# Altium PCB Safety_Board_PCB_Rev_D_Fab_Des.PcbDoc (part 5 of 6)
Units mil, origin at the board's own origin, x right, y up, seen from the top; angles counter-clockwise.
Board outline 11000 x 4400 mil, 6 copper layers (L1-TOP, L2-Plane, L3-Signal, L4-Signal, L5-Plane, L6-BOT); 712 components, 540 nets, 2214 pads, 875 vias.
Unrouted connection lines stored in the file: 3.
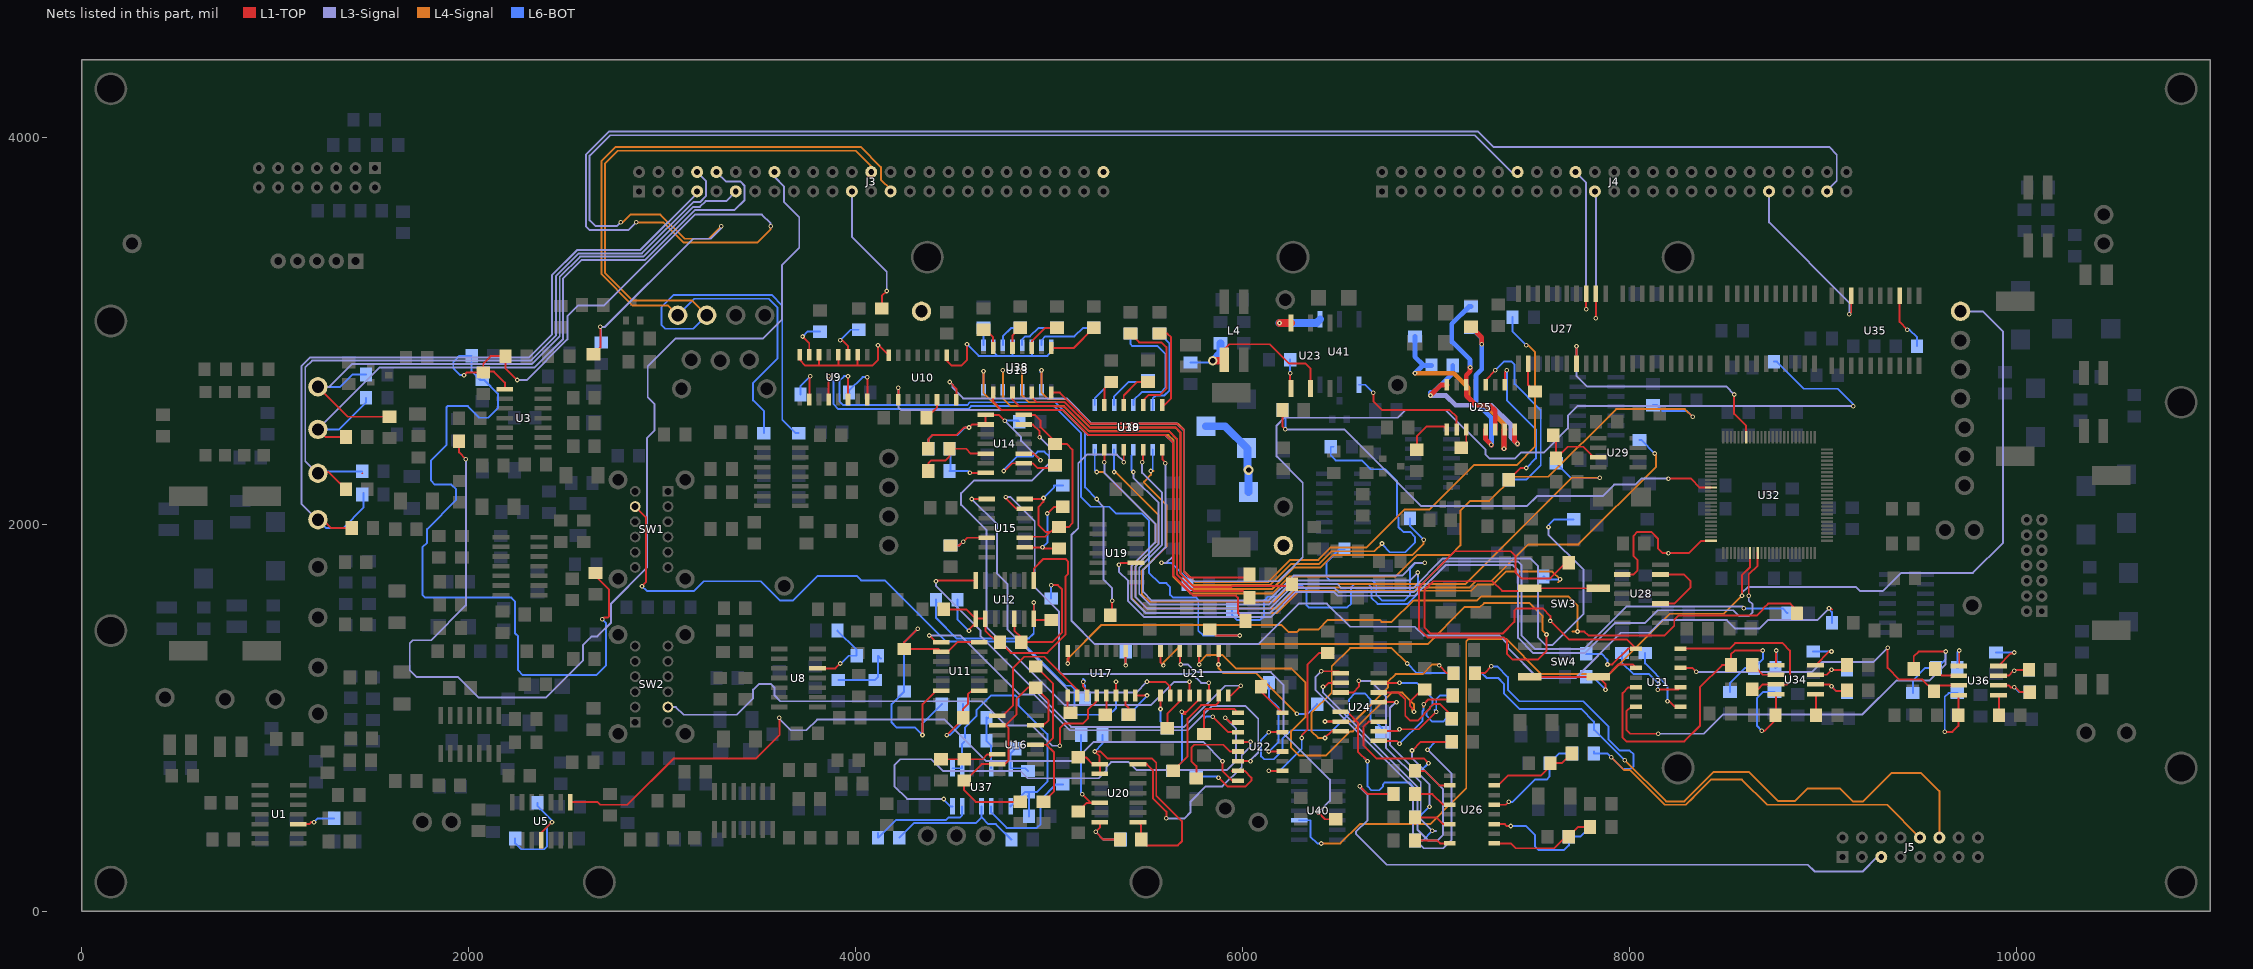
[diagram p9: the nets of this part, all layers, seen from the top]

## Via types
v1: diameter 24, hole 12, L1-TOP to L6-BOT, 720 vias
v2: diameter 50, hole 28, L1-TOP to L6-BOT, 138 vias
v3: diameter 28, hole 50, L1-TOP to L6-BOT, 17 vias

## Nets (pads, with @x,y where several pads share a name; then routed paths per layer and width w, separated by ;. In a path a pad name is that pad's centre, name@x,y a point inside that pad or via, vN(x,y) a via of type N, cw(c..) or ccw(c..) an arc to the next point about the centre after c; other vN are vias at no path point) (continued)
NetR83_2: R83.2 R266.1 R271.2 U11.2 U11.6 U11.14 | length 1737.2
  L1-TOP w10: v1(4320,1460) 4250,1390 R83.2@4250,1355.24 4426.46,1355.24 U11.2@4441.57,1340.12 4475,1340.12 4525,1390.12 U11.14@4638.43,1390.12 ; v1(4345,910.12) 4345,1070.12 U11.6@4415,1140.12
  L6-BOT w10: v1(4320,1460) 4250,1390 R266.1@4250,1135.24 4185,1070.24 4185,975 4210,950 4305.12,950 v1(4345,910.12) 4345,970.12 R271.2@4444.88,1070
NetR85_1: R85.1 U10.14 | length 115.7
  L1-TOP w10: R85.1@4364.88,2550 4420,2605.12 U10.14@4420,2642.84
NetR86_1: R86.1 R87.2 U14.5 | length 401.4
  L1-TOP w10: R87.2@4374.88,2275 4374.88,2314.88 4390,2330 4465,2330 4485.12,2350.12 R86.1@4485.12,2390 4485.24,2389.88 4570.12,2389.88 4595,2365 U14.5@4671.57,2365
NetR86_2: R86.2 R267.2 R276.1 U14.1 U14.2 U14.10 | length 1311.2
  L1-TOP w10: R86.2@4374.88,2390 4374.88,2439.88 4395,2460 4520,2460 4560,2500 v1(4585,2500) 4600,2515 U14.2@4671.57,2515 U14.1@4671.57,2565 ; U14.1@4666.69,2560.12 U14.1@4671.57,2565 ; v1(4770,2535) 4740,2565 U14.1@4671.57,2565 ; U14.10@4868.43,2365 4920,2365 v1(4955,2330)
  L3-Signal w10: v1(4770,2535) 4855,2450 4855,2430 v1(4955,2330)
  L6-BOT w10: R267.2@4374.88,2390 4374.88,2439.88 4395,2460 4525,2460 4565,2500 v1(4585,2500) ; v1(4770,2535) 4839.88,2535 R276.1@4844.88,2530 ; R276.1@4829.88,2535 R276.1@4844.88,2520
NetR89_1: R89.1 R269.2 U15.5 | length 311.5
  L1-TOP w10: R89.1@4514.88,1915 R89.1@4490,1890.12 4535.12,1890.12 4575,1930 U15.5@4676.57,1930
  L6-BOT w10: R269.2@4490,1890.12 4535.12,1890.12 v1(4555,1910)
NetR90_1: R90.1 R96.2 R265.2 U12.1 U12.2 U12.8 | length 1707.4
  L1-TOP w10: R90.1@4455.12,1560 4571.57,1560 U12.1@4620,1511.57 ; v1(4585,1450) 4585,1455 4620,1490 U12.1@4620,1511.57 ; U12.8@4920,1708.43 4920,1770 4970,1820 5085,1820 5098,1807 5098,1743 5085,1730 5085,1430 4990,1335 4799.88,1335 R96.2@4744.88,1390 4730,1390 4670,1450 U12.2@4670,1511.57 U12.1@4620,1511.57
  L6-BOT w10: R265.2@4525.12,1610 4525.12,1509.88 v1(4585,1450)
NetR91_2: R91.2 R94.1 U16.5 | length 322.9
  L1-TOP w10: R91.2@4440,785.12 4655.12,785.12 4680,810 U16.5@4731.57,810 ; 4695.12,795.12 U16.5@4710,810
NetR92_2: R92.2 R271.1 U11.9 | length 526.4
  L1-TOP w10: v1(4470,910) 4555.12,995.12 4555.12,1045.24 4580,1070.12 4580,1120.12 4600,1140.12 U11.9@4638.43,1140.12
  L6-BOT w10: v1(4470,910) 4485,910 4555.12,980.12 R271.1@4555.12,1070
NetR93_1: R93.1 U13.7 | length 125.4
  L1-TOP w10: R93.1@4660,3014.88 4710,2964.88 U13.7@4710,2910.16
NetR94_2: R94.2 R98.2 R99.1 U16.2 U16.6 U16.13 | length 1382.6
  L1-TOP w10: U16.2@4731.57,960 4775,960 ; R99.1@4850,565.12 4619.88,565.12 4560,625 R94.2@4560,674.88 4564.88,674.88 4650,760 4770,760 4790,780 4790,945 4775,960 ; U16.13@4970,960 4995,985 4995,1089.88 R98.2@4930,1154.88 4889.88,1154.88 4830,1095 4830,1015 4775,960
NetR95_1: R95.1 U13.5 | length 121.3
  L1-TOP w10: U13.5@4810,2910.16 4810,2974.88 R95.1@4850,3014.88
NetR96_1: R96.1 R281.2 U12.5 | length 724.9
  L1-TOP w10: U12.5@4820,1511.57 4820,1450 4855.12,1414.88 R96.1@4855.12,1390 5015,1390 5065,1440 5065,1665 5045,1685 v1(5010,1685)
  L6-BOT w10: R281.2@5010,1615.12 v1(5010,1685)
NetR97_1: R97.1 R104.2 U15.9 | length 501.1
  L1-TOP w10: U15.9@4873.43,1880 v1(4965,1880) 4970.12,1874.88 R97.1@5050,1874.88 ; v1(4990,2055) 5024.88,2089.88 R104.2@5070,2089.88 ; R97.1@5039.88,1880 R97.1@5070,1849.88
  L6-BOT w10: v1(4965,1880) 4990,1905 v1(4990,2055)
NetR97_2: R97.2 R103.2 R283.1 U14.14 U15.10 U15.14 | length 1466.5
  L1-TOP w10: U14.14@4868.43,2565 4925,2565 4955,2535 4955,2500 5030,2425 R103.2@5030,2415.12 5089.88,2415.12 5120,2385 5120,2005 5100.12,1985.12 5030.12,1985.12 4980,1935 4878.43,1935 U15.10@4873.43,1930 ; U15.14@4873.43,2130 4965,2130 v1(4970,2135) 4970,2115 4945,2090 4945,1995 4979.88,1960.12 5005.12,1960.12
  L6-BOT w10: v1(4970,2135) 5025.12,2190.12 5025.12,2200.12 R283.1@5070,2200.12
NetR98_1: R98.1 R100.2 U16.11 | length 847.7
  L1-TOP w10: U16.11@4928.43,860 4985,860 ; R98.1@4930,1265.12 5020,1175.12 5020,895 4985,860 ; R100.2@4970,565.12 5025,620.12 5025,820 4985,860
NetR101_1: R101.1 U13.3 | length 193.8
  L1-TOP w10: U13.3@4910,2910.16 4910,2945 4979.88,3014.88 R101.1@5040,3014.88
NetR102_2: R102.2 R265.1 U12.7 | length 997.2
  L1-TOP w10: U12.7@4915,1516.57 U12.7@4920,1511.57 v1(4920,1595) ; U12.7@4920,1511.57 4926.69,1504.88 R102.2@5010,1504.88
  L6-BOT w10: R265.1@4414.88,1610 4414.88,1515.12 4520,1410 4895,1410 4920,1435 v1(4920,1595)
NetR103_1: R103.1 R282.2 U14.9 | length 645.3
  L1-TOP w10: v1(4765,2275) 4770,2275 4810,2315 4915,2315 4940,2290 5015.12,2290 R103.1@5030,2304.88
  L6-BOT w10: v1(4765,2275) 4765,2280 4835,2350 4915,2350 4940,2375 4975,2375 5000,2350 5000,2334.88 R282.2@5030,2304.88
NetR105_1: R105.1 U17.1 | length 95.9
  L1-TOP w10: U17.1@5095,1114.84 5095,1040.12 R105.1@5110,1025.12
NetR106_1: R106.1 R115.2 R289.2 U20.1 U20.2 U20.8 | length 1499.2
  L1-TOP w10: R106.1@5150,795.12 5189.88,795.12 5225,760 U20.1@5261.57,760 U20.2@5261.57,710 ; U20.1@5260,760 5260,800 v1(5235,825) 5265,825 5300,790 5530,790 5553,767 5553,597 5685,465 5685,360 5665,340 5505.12,340 R115.2@5475.12,370 ; U20.8@5458.43,460 5475.12,443.31 R115.2@5475.12,370 ; R115.2@5490,370 R115.2@5475.12,370
  L6-BOT w10: v1(5235,825) 5275.12,865.12 R289.2@5275.12,910
NetR107_2: R107.2 R289.1 U20.5 | length 500.9
  L1-TOP w10: R107.2@5150,515.12 5194.88,560 U20.5@5261.57,560 ; v1(5170,605) 5215,560
  L6-BOT w10: R289.1@5164.88,910 5164.88,610.12 v1(5170,605)
NetR108_1: R108.1 U13.1 | length 263.4
  L1-TOP w10: U13.1@5010,2910.16 5125.28,2910.16 R108.1@5230,3014.88
NetR109_2: R109.2 U9.14 | length 2636.3
  L1-TOP w10: U9.14@3960,2644.84 v1(3960,2765) ; R109.2@5315.12,1530 5325,1539.88 v1(5325,1605)
  L3-Signal w10: v1(5245,2130) 5245,2125 5280,2090 5280,1715 5325,1670 v1(5325,1605)
  L6-BOT w10: v1(3960,2765) 3940,2765 3915,2740 3915,2635 3935,2615 4575,2615 4590,2630 5030,2630 5185,2475 5185,2190 v1(5245,2130)
NetR110_1: R110.1 U17.5 | length 101.8
  L1-TOP w10: R110.1@5290,1015.12 5295,1020.12 U17.5@5295,1114.84
NetR111_1: R111.1 U18.7 | length 134.2
  L1-TOP w10: U18.7@5285,2615.16 5285,2699.88 R111.1@5320,2734.88
NetR112_1: R112.1 U18.3 | length 598.6
  L1-TOP w10: R112.1@5420,2984.88 5464.88,2940 5580,2940 5605,2915 5605,2700 5573,2668 5513,2668 5485,2640 U18.3@5485,2615.16
NetR114_2: R114.2 U17.7 | length 105.9
  L1-TOP w10: U17.7@5395,1114.84 5395,1065 5410,1050 R114.2@5410,1015.12
NetR115_1: R115.1 R293.2 U20.7 | length 348.3
  L1-TOP w10: v1@5242.5,412.5 5261.57,431.57 U20.7@5261.57,460 ; v1@5245,410 v1(5240,410) 5280,370 R115.1@5364.88,370
  L6-BOT w10: v1(5240,410) 5280,370 R293.2@5369.88,370
NetR116_1: R116.1 U18.5 | length 203.8
  L1-TOP w10: U18.5@5385,2615.16 5385,2665 5454.88,2734.88 R116.1@5510,2734.88
NetR118_1: R118.1 U18.1 | length 442.7
  L1-TOP w10: R118.1@5570,2984.88 5610.12,2984.88 5630,2965 5630,2650 5595.16,2615.16 U18.1@5585,2615.16
NetR119_1: R119.1 U21.3 | length 213.8
  L1-TOP w10: R119.1@5610,935 5610,1020 5675,1085 U21.3@5675,1114.84 U21.3@5680,1109.84
NetR120_1: R120.1 U21.7 | length 530.8
  L1-TOP w10: R120.1@5640.12,725.24 5715,800.12 5715,995 5785,1065 5860,1065 5875,1080 U21.7@5875,1114.84
NetR121_1: R121.1 U22.5 | length 430.8
  L1-TOP w10: R121.1@5760,685.12 5760,750 5735,775 5735,845 5750,860 5900,860 5935,825 U22.5@5974.84,825
NetR122_1: R122.1 U22.1 | length 322.3
  L1-TOP w10: R122.1@5815.12,915.12 R122.1@5800,915.12 5800,1035 5810,1045 5954.84,1045 U22.1@5974.84,1025
NetR123_2: R123.2 U9.12 | length 3518
  L1-TOP w10: U9.12@3860,2644.84 v1(3860,2765) ; R123.2@5830,1454.88 5859.88,1425 v1(5985,1425)
  L6-BOT w10: v1(3860,2765) 3860,2760 3885,2735 3885,2620 3910,2595 4580.96,2595 4595.96,2610 5025,2610 ; 5025,2609.04 5165,2469.04 5165,2140 5215,2090 5310,2090 5345,2055 5480,2055 5515,2020 5515,1750 5570,1695 5605,1695 5625,1675 5625,1635 5640,1620 5760,1620 5770,1610 5770,1450 5795,1425 v1(5985,1425)
NetR124_2: R124.2 U13.10 | length 2268.1
  L1-TOP w10: U13.10@4710,2679.84 4710,2635 4755,2590 5072.88,2590 5202.88,2460 5600,2460 5640,2420 5640,1735 5730,1645 5730.96,1645 5745,1630.96 5964.04,1630.96 5975,1620 5975,1539.88 R124.2@6014.88,1500
NetR125_2: R125.2 U13.16 | length 1859.1
  L1-TOP w10: U13.16@5010,2675 U13.16@5010,2679.84 5055.16,2679.84 5215,2520 5660,2520 5695,2485 5695,1755 5725,1725 6019.88,1725 R125.2@6034.88,1740
NetR126_2: R126.2 U13.12 | length 2095.7
  L1-TOP w10: U13.12@4810,2679.84 4810,2645 4845,2610 5025.96,2610 5025.96,2609.04 5077.88,2609.04 5206.92,2480 5620,2480 5661,2439 5661,2251 5660,2250 5660,1740 5745,1655 5999.88,1655 R126.2@6034.88,1620
NetR127_2: R127.2 U22.16 | length 180.8
  L1-TOP w10: R127.2@6094.88,1160 6094.88,1135.12 6134.72,1095.28 6134.88,1095.28 U22.16@6205.16,1025
NetR131_2: R131.2 U13.14 | length 2209.5
  L1-TOP w10: U13.14@4910,2679.84 4910,2655 4935,2630 5080.96,2630 5210.96,2500 5655,2500 5678,2477 5678,1747 5750,1675 5940,1675 5945,1680 6244.88,1680 R131.2@6254.88,1690
NetR133_2: R133.2 U21.14 | length 1537.5
  L1-TOP w10: U21.14@5675,1345.16 5675,1275 v1(5680,1275) ; v1(6390,510) 6425.12,474.88 R133.2@6480,474.88
  L3-Signal w10: v1(5680,1275) 5715,1275 5755,1235 6145,1235 6210,1170 6210,920 6450,680 6450,570 v1(6390,510)
NetR137_2: R137.2 U22.10 | length 865
  L1-TOP w10: v1(6135,725) U22.10@6205.16,725 ; v1(6305,895) 6305,910 6335,940 6335,1275 6394.88,1334.88 R137.2@6440,1334.88
  L6-BOT w10: v1(6135,725) 6190,725 6305,840 v1(6305,895)
NetR138_2: R138.2 U26.10 | length 210.8
  L1-TOP w10: R138.2@6890.12,725 6940,725 7015,650 U26.10@7069.84,650
NetR139_2: R139.2 U26.12 | length 202.5
  L1-TOP w10: R139.2@6890.12,605 6980,605 7035,550 U26.12@7069.84,550
NetR140_2: R140.2 U26.14 | length 194.2
  L1-TOP w10: R140.2@6890.12,485 7000,485 7035,450 U26.14@7069.84,450
NetR141_2: R141.2 U26.16 | length 185.9
  L1-TOP w10: R141.2@6890.12,365 7005,365 7020,350 U26.16@7069.84,350
NetR145_1: R145.1 U25.1 | length 251.9
  L1-TOP w10: R145.1@6900,2385.12 6900,2455 6950,2505 7039.84,2505 U25.1@7055,2489.84
NetR147_2: R147.2 U21.12 | length 2101.1
  L1-TOP w10: v1(5775,1275) U21.12@5775,1345.16 ; v1(6885,1030) 6885,1040 6865,1060 6865,1085 6924.88,1144.88 R147.2@6940,1144.88
  L4-Signal w10: v1(5775,1275) 5775,1285 5815,1325 5895,1325 5965,1255 6250,1255 6325,1180 6325,1005 6250,930 6250,845 6290,805 6430.96,805 6555,929.04 6569.04,929.04 6770,1130 6825,1130 6885,1070 v1(6885,1030) 6875,1040
NetR148_2: R148.2 U24.14 | length 564.2
  L1-TOP w10: U24.14@6703.43,1130 6805,1130 6840,1095 6840,1010 6865,985 6904.64,985 6967.71,1048.07 6967.71,1052.71 6985,1070 7020,1070 7079.88,1010.12 R148.2@7079.88,995
NetR149_2: R149.2 U24.2 | length 1937.8
  L1-TOP w10: v1(6415,1160) 6425,1160 6445,1180 U24.2@6506.57,1180 ; v1(6875,830) 6920,875 R149.2@7079.88,875
  L3-Signal w10: v1(6415,1160) 6415,1130 6903,642 6903,422 6960,365 7005,365 7035,395 7035,630 6875,790 v1(6875,830) v1@6870,830
NetR151_2: R151.2 R335.1 U25.5 | length 912.9
  L1-TOP w25: R151.2@7180,3000 R151.2@7180,3019.88 7235,2964.88 v1(7235,2930) ; U25.5@7255,2489.84 7255,2440 v1(7285,2410)
  L6-BOT w25: R335.1@7180,3000 R335.1@7180,3014.88 7235,2959.88 7235,2800 7205,2770 7205,2630 7285,2550 v1(7285,2410)
NetR152_1: R152.1 U25.3 | length 105.1
  L1-TOP w10: R152.1@7130,2395.12 7155,2420.12 U25.3@7155,2489.84
NetR154_2: R154.2 U24.6 | length 904.9
  L1-TOP w10: v1(6425,980) U24.6@6506.57,980 ; v1(7015,1270) 7055,1230 R154.2@7089.88,1230
  L4-Signal w10: v1(6425,980) 6575,980 6750,1155 6750,1185 6790,1225 6930,1225 6980,1275 7010,1275 v1(7015,1270)
NetR155_2: R155.2 U24.9 | length 558
  L1-TOP w10: U24.9@6703.43,880 6795,880 v1(6810,865) ; v1(6935,1070) 6960,1095 7064.88,1095 R155.2@7084.88,1115 R155.2@7080,1115
  L4-Signal w10: 6935,1055 v1(6935,1070)
  L6-BOT w10: v1(6810,865) 6930,985 6930,1034.04 6935,1039.04 v1(6935,1070)
NetR157_1: R157.1 U25.10 | length 781.6
  L1-TOP w10: U25.10@7355,2720.16 7355,2785 v1(7365,2795) ; R157.1@7375.12,2230 7435.12,2290 v1(7465,2290)
  L6-BOT w10: v1(7365,2795) 7365,2640 7515,2490 7515,2340 v1(7465,2290)
NetR159_2: R159.2 R166.2 U26.7 | length 476.8
  L1-TOP w10: U26.7@7300.16,650 7320,650 7370,700 7540,700 7590.12,750.12 R159.2@7590.12,765 7649.88,765 R166.2@7699.88,815
NetR160_2: R160.2 R168.2 U26.1 | length 550.6
  L1-TOP w10: U26.1@7300.16,350 7385,350 7410,325 7610,325 7670,385 R160.2@7685.12,385 7735.12,435 R168.2@7794.88,435
NetR161_2: R161.2 U27.2 | length 158.3
  L1-TOP w10: U27.2@7475,2828.9 7475,2720.12 R161.2@7510,2685.12
NetR162_2: R162.2 R163.1 U29.7 | length 391.6
  L1-TOP w10: R162.2@7604.88,2460 7619.72,2445.16 R163.1@7619.72,2340.04 7679.72,2400.04 7759.96,2400.04 7814.96,2345.04 U29.7@7837.6,2345.04
NetR164_2: R164.2 U21.16 | length 4373
  L1-TOP w10: U21.16@5575,1325 5575,1285 v1(5590,1270) ; v1(7570,1430) 7570,1345 7525,1300 7395,1300 7365,1330 7365,1400 7350,1415 6955,1415 6910,1460 6910,1675 7095,1860 7385,1860 7410,1835 7410,1750 7440,1720 7590,1720 7670,1800 R164.2@7685.12,1800
  L4-Signal w10: v1(5590,1270) 5590,1285 5685,1380 6955,1380 7146,1571 7226,1571 7247,1592 7483,1592 7550,1525 7550,1450 v1(7570,1430)
NetR171_1: R171.1 U31.16 U34.7 | length 963.8
  L1-TOP w10: U31.16@8263.12,1356.92 8516.92,1356.92 8545,1385 8790,1385 8827.96,1347.04 8827.96,1186.92 8812.96,1171.92 8687.96,1171.92 8662.96,1146.92 R171.1@8633.08,1146.92
NetR172_1: R172.1 R363.1 R364.1 U31.5 | length 1716.1
  L1-TOP w10: U31.5@8032.81,1156.92 7992.96,1156.92 7962.96,1126.92 7962.96,896.92 7982.96,876.92 8282.96,876.92 8362.96,956.92 8362.96,1156.92 8477.96,1271.92 R172.1@8522.85,1271.92 ; R172.1@8522.85,1256.92 8522.85,1326.8 8542.96,1346.92 v1(8687.96,1346.92)
  L6-BOT w10: R364.1@8517.96,1132.04 8517.96,1176.92 8597.96,1256.92 R363.1@8642.85,1256.92 8687.96,1302.04 v1(8687.96,1346.92)
NetR172_2: R172.2 U34.6 | length 137
  L1-TOP w10: R172.2@8633.08,1256.92 8652.96,1256.92 8687.96,1221.92 U34.6@8755.6,1221.92
NetR173_1: R173.1 R366.2 U34.8 | length 511.7
  L1-TOP w10: v1(8682.96,931.92) 8697.96,931.92 8753.08,987.04 8753.08,1016.92 8755.6,1019.44 U34.8@8755.6,1121.92
  L6-BOT w10: v1(8682.96,931.92) 8657.96,956.92 8657.96,1101.92 8688.08,1132.04 R366.2@8747.96,1132.04
NetR174_2: R174.2 U17.16 | length 4310.5
  L1-TOP w10: v1(5095,1280) 5100,1285 U17.16@5100,1315 ; v1(7730,1445) 7765.96,1445 7785.96,1425 8180,1425 8230,1475 8230,1505 8252,1527 8657,1527 8690,1560 8690,1565 8715,1590 8830,1590 8865.12,1554.88 R174.2@8865.12,1540
  L4-Signal w10: v1(5095,1280) 5095,1305 5270,1480 6200,1480 6238,1442 6277.96,1442 6290.96,1455 6390,1455 6440,1505 6708,1505 6718,1495 6770,1495 6880,1605 7210,1605 7231,1626 7684,1626 7730,1580 v1(7730,1445) 7705,1445
NetR175_1: R175.1 U34.1 | length 105
  L1-TOP w10: U34.1@8962.73,1121.92 8962.85,1121.8 R175.1@8962.85,1016.92
NetR177_1: R177.1 R373.2 U34.3 | length 252.8
  L1-TOP w10: U34.3@8960.33,1221.92 9017.96,1221.92 v1(9042.96,1246.92) R177.1@9122.85,1246.92
  L6-BOT w10: v1(9042.96,1246.92) R373.2@9122.85,1246.92
NetR178_1: R178.1 R375.2 U34.2 | length 267.3
  L1-TOP w10: U34.2@8960.33,1171.92 9032.96,1171.92 9067.96,1136.92 R178.1@9122.85,1136.92
  L6-BOT w10: v1(9042.96,1161.92) 9067.96,1136.92 R375.2@9122.85,1136.92
NetR182_1: R182.1 U31.14 U36.7 | length 1644.8
  L1-TOP w10: U31.14@8282.96,1256.92 8322.96,1256.92 v1(8342.96,1236.92) ; v1(9332.96,1361.92) 9332.96,1256.92 9392.96,1196.92 9512.96,1196.92 9572.96,1136.92 R182.1@9573.08,1136.92 9603.08,1166.92 U36.7@9700.6,1166.92
  L3-Signal w10: v1(8342.96,1236.92) 8942.96,1236.92 8992.96,1286.92 9257.96,1286.92 v1(9332.96,1361.92)
NetR183_1: R183.1 R377.1 R378.1 U31.7 | length 2588.4
  L1-TOP w10: U31.7@8032.81,1056.92 8007.96,1056.92 7982.96,1031.92 7982.96,936.92 8002.96,916.92 v1(8147.96,916.92) ; R183.1@9467.85,1251.92 9467.85,1316.8 9492.96,1341.92 v1(9632.96,1341.92)
  L3-Signal w10: v1(8147.96,916.92) 8382.96,916.92 8482.96,1016.92 9202.96,1016.92 9377.96,1191.92 9547.96,1191.92 9632.96,1276.92 v1(9632.96,1341.92)
  L6-BOT w10: R378.1@9462.96,1127.04 9462.96,1191.92 9527.96,1256.92 9587.96,1256.92 9632.96,1301.92 v1(9632.96,1341.92)
NetR183_2: R183.2 U36.6 | length 137
  L1-TOP w10: R183.2@9578.08,1251.92 9613.08,1216.92 U36.6@9700.6,1216.92
NetR184_1: R184.1 R379.2 U36.8 | length 496.9
  L1-TOP w10: v1(9627.96,926.92) 9667.96,926.92 9698.08,957.04 9698.08,1114.4 U36.8@9700.6,1116.92
  L6-BOT w10: v1(9627.96,926.92) 9627.96,1106.92 9648.08,1127.04 R379.2@9692.96,1127.04
NetR185_1: R185.1 U36.1 | length 106
  L1-TOP w10: U36.1@9905.33,1116.92 9907.85,1114.4 R185.1@9907.85,1011.92
NetR186_1: R186.1 R384.2 U36.3 | length 246.9
  L1-TOP w10: U36.3@9905.33,1216.92 9957.96,1216.92 9982.96,1241.92 v1(9987.96,1241.92) 9992.96,1246.92 R186.1@10062.85,1246.92
  L6-BOT w10: v1(9987.96,1241.92) 9992.96,1246.92 R384.2@10062.85,1246.92
NetR187_1: R187.1 R385.2 U36.2 | length 267.3
  L1-TOP w10: U36.2@9905.33,1166.92 9957.96,1166.92 9967.96,1156.92 9992.96,1156.92 10017.96,1131.92 R187.1@10067.85,1131.92
  L6-BOT w10: v1(9987.96,1156.92) 10012.96,1131.92 R385.2@10067.85,1131.92
NetR200_2: R200.2 U1.10 | length 198.9
  L1-TOP w10: U1.10@1118.43,450 1175,450 1185,460 v1(1200,460)
  L6-BOT w10: v1(1200,460) 1220,480 R200.2@1304.88,480
NetR217_1: R217.1 R225.2 U5.11 | length 632.8
  L1-TOP w10: U5.11@2375,325 2375,405 v1(2430,460)
  L6-BOT w10: R217.1@2239.88,375 2239.88,350.12 2270,320 2390,320 2405,335 2405,435 v1(2430,460) 2430,470 2355.12,544.88 R225.2@2355.12,560
NetR250_2: R250.2 U9.10 | length 238
  L1-TOP w10: U9.10@3760,2644.84 3760,2760 v1(3765,2765)
  L6-BOT w10: R250.2@3714.88,2670 3714.88,2714.88 v1(3765,2765)
NetR253_2: R253.2 U9.7 | length 208.8
  L1-TOP w10: v1(3725.12,2969.88) 3759.57,2935.43 U9.7@3759.57,2875.59
  L6-BOT w10: v1(3725.12,2969.88) 3750.12,2994.88 R253.2@3815,2994.88
NetR255_2: R255.2 R262.2 U8.12 | length 401.3
  L1-TOP w10: U8.12@3801.85,1255 3895,1255 v1(3920,1280)
  L6-BOT w10: R255.2@3905.12,1450 4004.88,1350.24 R262.2@4004.88,1320 3965,1320 3925,1280 v1(3920,1280)
NetR258_1: R258.1 R262.1 R263.2 | length 342.2
  L6-BOT w10: R258.1@3910,1195.12 R263.2@4100,1195.12 4115.12,1210.24 R262.1@4115.12,1320 R262.1@4130,1305.12
NetR260_2: R260.2 U9.3 | length 215
  L1-TOP w10: v1(3920,2950) 3930,2950 3960,2920 U9.3@3960,2875.16
  L6-BOT w10: v1(3920,2950) 3974.88,3004.88 R260.2@4015,3004.88
NetR261_2: R261.2 U9.16 | length 249.2
  L1-TOP w10: U9.16@4060,2644.84 v1(4060,2760)
  L6-BOT w10: R261.2@3964.88,2680 3964.88,2689.88 4035,2760 v1(4060,2760)
NetR264_1: R264.1 R275.2 U37.11 | length 727.5
  L6-BOT w10: R264.1@4225.12,380 4300.12,455 4620,455 4650,485 ; U37.11@4650,541.57 4650,485 ; R275.2@4804.88,370 4724.67,450.21 4684.79,450.21 4650,485
NetR264_2: R264.2 U37.13 | length 554.2
  L6-BOT w10: R264.2@4114.88,404.88 R264.2@4114.88,380 4116,380 4208,472 4467,472 4480,485 4540,485 4550,495 U37.13@4550,541.57
NetR267_1: R267.1 R268.2 U14.7 | length 307.5
  L1-TOP w10: v1(4590,2265) U14.7@4671.57,2265
  L6-BOT w10: R267.1@4490,2389.88 4490,2279.88 R268.2@4485.12,2275 4580,2275 v1(4590,2265)
NetR270_1: R270.1 R273.2 U37.5 | length 285.8
  L6-BOT w10: R273.2@4674.88,1000 4674.88,880.24 4700,855.12 U37.5@4700,738.43 ; R273.2@4675.12,990.24 R273.2@4684.88,1000
NetR270_2: R270.2 R278.2 R279.1 U37.1 U37.2 U37.8 | length 1507.5
  L6-BOT w10: U37.1@4500,738.43 U37.2@4550,738.43 4550,865.12 R270.2@4564.88,880 4564.88,949.88 4625,1010 4625,1040 4700,1115 4825,1115 4840,1100 4840,1065 4990,915 4990,670 4934.88,614.88 4873.31,614.88 U37.8@4800,541.57 U37.8@4800,545 ; R278.2@4890,594.88 R278.2@4894.88,590 ; R278.2@4890,614.88 4894.88,610 R279.1@4894.88,490
NetR272_1: R272.1 U38.1 | length 89.7
  L6-BOT w10: U38.1@4660,2925.16 R272.1@4660,3014.88
NetR274_1: R274.1 U38.3 | length 153.4
  L6-BOT w10: U38.3@4760,2925.16 4760,2970 4804.88,3014.88 R274.1@4850,3014.88
NetR277_2: R277.2 R278.1 U37.7 | length 207.4
  L6-BOT w10: R277.2@4824.88,840 4824.88,839.88 4800,815 U37.7@4800,738.43 4876.69,738.43 R278.1@4890,725.12
NetR280_1: R280.1 U38.5 | length 234.6
  L6-BOT w10: U38.5@4860,2925.16 4860,2955 4875,2970 4900,2970 4944.88,3014.88 R280.1@5040,3014.88
NetR284_1: R284.1 U17.3 | length 181.9
  L1-TOP w10: v1(5175,1185) 5175,1160 5195,1140 U17.3@5195,1114.84
  L6-BOT w10: v1(5175,1185) 5175,1175 5185.12,1164.88 R284.1@5185.12,1100 ; 5175,1200 v1@5185.12,1189.88
NetR285_2: R285.2 U37.10 | length 601.1
  L6-BOT w10: U37.10@4700,541.57 4700,510 4780,430 4935,430 4955,450 4955,575 5034.88,654.88 R285.2@5070,654.88
NetR286_1: R286.1 U38.7 | length 321.7
  L6-BOT w10: U38.7@4960,2925.16 4960,2950 4980,2970 5130,2970 5174.88,3014.88 R286.1@5230,3014.88
NetR288_1: R288.1 U17.10 | length 145.2
  L1-TOP w10: v1(5395,1270) U17.10@5395,1345.16
  L6-BOT w10: R288.1@5394.88,1340 5394.88,1270.12 v1(5395,1270)
NetR290_1: R290.1 U39.1 | length 154.9
  L6-BOT w10: U39.1@5235,2615.16 5235,2649.88 R290.1@5320,2734.88
NetR291_1: R291.1 U39.5 | length 647.4
  L6-BOT w10: R291.1@5420,2984.88 5420,2930 5430,2920 5560,2920 5600,2880 5600,2705 5578,2683 5478,2683 5435,2640 U39.5@5435,2615.16
NetR292_2: R292.2 U17.8 | length 199.3
  L1-TOP w10: U17.8@5445,1114.84 5499.84,1114.84 5500,1115 v1(5505,1115)
  L6-BOT w10: R292.2@5410,1015.12 5505,1110.12 v1(5505,1115)
NetR294_1: R294.1 U39.3 | length 255
  L6-BOT w10: U39.3@5335,2615.16 5335,2660 5409.88,2734.88 5500,2734.88 R294.1@5510,2744.88
NetR296_1: R296.1 U21.5 | length 465.5
  L1-TOP w10: v1(5685,1030) 5710,1030 5775,1095 U21.5@5775,1105 ; v1@5690,1020 5705,1020
  L6-BOT w10: R296.1@5640,725.12 5640.12,725.12 5685,770 v1(5685,1030)
NetR297_1: R297.1 U39.7 | length 477.2
  L6-BOT w10: U39.7@5535,2590 5535,2650 5550,2665 5595,2665 5620,2690 5620,2934.88 R297.1@5570,2984.88
NetR299_1: R299.1 U21.1 | length 184.2
  L1-TOP w10: v1(5575,1045) U21.1@5575,1114.84
  L6-BOT w10: v1(5575,1045) 5575,980.12 R299.1@5610,945.12
NetR300_2: R300.2 U10.10 | length 2513.4
  L1-TOP w10: U10.10@4220,2642.84 v1(4220,2705)
  L3-Signal w10: v1(4220,2705) 4220,2605 4235,2590 5071.92,2590 5200,2461.92 5598.08,2461.92 5640,2420 5640,1835 5605,1800 v1(5580,1800)
  L6-BOT w10: v1(5580,1800) 5630,1800 5714.88,1715.12 R300.2@5714.88,1690
NetR303_2: R303.2 U18.14 | length 3907.2
  L1-TOP w10: v1(5480,2320) 5480,2325 5485,2330 U18.14@5485,2384.84
  L3-Signal w10: v1(5480,2320) 5480,2265 5583,2162 5583,1893 5465,1775 5465,1640 5520,1585 6136.92,1585 6261.92,1710 6865,1710 v1(6905,1750) 6905,1730
  L6-BOT w10: R303.2@5945.12,1560 5945.12,1529.88 5970,1505 6090,1505 6110,1525 6110,1605 6130,1625 6175,1625 6230,1680 6310,1680 6330,1660 6330,1580 6340,1570 6540,1570 6560,1590 6560,1675 6575,1690 6650,1690 6665,1675 6665,1620 6697.02,1587.98 6852.98,1587.98 6905,1640 v1(6905,1750)
NetR304_1: R304.1 U22.3 | length 292
  L1-TOP w10: v1(5845,1005) 5925,925 U22.3@5974.84,925
  L6-BOT w10: R304.1@5800,915.12 5800,995 5810,1005 v1(5845,1005)
NetR305_1: R305.1 U22.7 | length 447.7
  L1-TOP w10: v1(5875,690) 5920,645 6015,645 6045,675 6045,690 6010,725 U22.7@5945,725
  L6-BOT w10: R305.1@5760,695.12 5869.88,695.12 v1(5875,690)
NetR309_2: R309.2 U22.12 | length 466.6
  L1-TOP w10: v1(6135,825) U22.12@6205.16,825
  L6-BOT w10: R309.2@6134.88,1180 6134.88,1100.12 6185,1050 6185,875 v1(6135,825)
NetR310_1: R310.1 U23.1 | length 156.5
  L1-TOP w10: v1(6245,2780) 6245,2705.71 U23.1@6250,2700.71
  L6-BOT w10: v1(6245,2780) 6245.12,2780.12 R310.1@6245.12,2850 ; R310.1@6245.12,2824.88 R310.1@6245.12,2830
NetR313_2: R313.2 U21.10 | length 718.1
  L1-TOP w10: v1(5875,1275) U21.10@5875,1345.16
  L4-Signal w10: v1(5875,1275) 5875,1255 5900,1230 6070,1230 v1(6280,1020)
  L6-BOT w10: v1(6280,1020) 6334.88,1020 R313.2@6384.88,1070
NetR314_2: R314.2 U18.16 | length 3297.2
  L1-TOP w10: U18.16@5585,2384.84 5585,2335 5605,2315 v1(5600,2315)
  L3-Signal w10: v1(5600,2315) 5600,1880 5485,1765 5485,1650 5530,1605 6132.88,1605 6262.5,1734.62 6824.62,1734.62 6890,1800 v1(6940,1800)
  L6-BOT w10: R314.2@6525.12,1870 6500,1870 6431.88,1801.88 6431.88,1727.04 6448.92,1710 6670,1710 6690,1690 6690,1635 6720,1605 6835,1605 6865,1635 6865,1770 6895,1800 v1(6940,1800)
NetR315_2: R315.2 U38.12 | length 4056.6
  L4-Signal w10: v1(4860,2795) 4860,2665 4895,2630 5080,2630 5210,2500 5651,2500 5678,2473 5678,1747 5740,1685 6140,1685 6250,1795 6395,1795 6455,1855 6455.96,1855 6460.96,1860 6680,1860 v1(6720,1900)
  L6-BOT w10: U38.12@4860,2694.84 v1(4860,2795) ; R315.2@6470,2400 R315.2@6454.88,2400 6454.88,2355.12 6480,2330 6615,2330 6661.19,2283.81 6736.19,2283.81 6798,2222 6798,2040.08 6805,2033.08 6805,1985 6830,1960 6865,1960 6890,1935 6890,1905 6840,1855 6760,1855 6720,1895 v1(6720,1900)
NetR318_1: R318.1 U24.11 | length 647.5
  L1-TOP w10: U24.11@6703.43,980 6650,980 6625,955 6625,855 6690,790 6935,790 v1(6960,765)
  L6-BOT w10: R318.1@6890.12,725 6920,725 v1(6960,765)
NetR319_1: R319.1 U24.5 | length 801.3
  L1-TOP w10: U24.5@6506.57,1030 6540,1030 6595,975 6595,825 v1(6645,775)
  L6-BOT w10: 6630,790 v1(6645,775) 6645,645 6665,625 6705,625 6725,645 6725,655 6735,665 6860,665 6890.12,634.88 R319.1@6890.12,605
NetR320_1: R320.1 U24.13 | length 831.6
  L1-TOP w10: U24.13@6703.43,1080 v1(6795,1080)
  L3-Signal w10: v1(6795,1080) 6790,1080 6760,1050 6760,860 6965,655 v1(6965,540)
  L6-BOT w10: R320.1@6890.12,485 6910,485 v1(6965,540)
NetR321_1: R321.1 U24.3 | length 1234
  L1-TOP w10: U24.3@6506.57,1130 6570,1130 6600,1160 v1(6600,1190)
  L3-Signal w10: v1(6600,1190) 6660,1190 6740,1110 6740,845 6920,665 6920,475 v1(6980,415) 7000,415
  L6-BOT w10: R321.1@6890.12,365 6930,365 v1(6980,415)
NetR325_2: R325.2 U22.14 | length 1219
  L1-TOP w10: v1(6135,925) U22.14@6205.16,925
  L6-BOT w10: v1(6135,925) 6095,885 6095,800 6110,785 6160,785 6205,830 6205,890 6250,935 6465,935 6550,1020 6550,1095 6580,1125 6630,1125 6660,1095 6660,990 6675,975 6690,975 6720,945 R325.2@6720,924.88
NetR326_2: R326.2 U38.14 | length 3500.2
  L4-Signal w10: v1(4760,2795) 4760,2650 4800,2610 5075.96,2610 5205,2480.96 5619.04,2480.96 5660,2440 5660,2250 5661,2249 5661,1739 5735,1665 6152.88,1665 6262.88,1775 6400,1775 6465,1840 6875.96,1840 6935,1899.04 v1(6935,1920)
  L6-BOT w10: U38.14@4760,2694.84 v1(4760,2795) ; R326.2@6864.88,2030 6864.88,1990.12 v1(6935,1920) v1@6930,1920
NetR327_2: R327.2 R333.1 U25.7 | length 1098.9
  L1-TOP w25: v1(7350,2390) 7350,2484.84 U25.7@7355,2489.84
  L4-Signal w25: v1(6890,2780) 7090,2780 7165,2705 7165,2655 7205,2615 7255,2615 7350,2520 v1(7350,2390)
  L6-BOT w25: v1(6890,2780) 6930,2820 R333.1@6974.88,2820 ; R327.2@6890,2969.88 6890,2865 6935,2820
NetR329_2: R329.2 U24.7 | length 1282.1
  L1-TOP w10: v1(6425,895) 6460,930 U24.7@6506.57,930
  L4-Signal w10: v1(6425,895) 6390,895 6355,930 6355,1025 6460,1130 6460,1265 6555,1360 6770,1360 v1(6850,1280)
  L6-BOT w10: v1(6850,1280) 6900,1230 R329.2@7089.88,1230
NetR330_2: R330.2 U24.10 | length 510.3
  L1-TOP w10: U24.10@6703.43,930 6800,930 v1(6810,940) 6910,940 v1(7000,1030)
  L6-BOT w10: 6990,1040 v1(7000,1030) 7000,1095 7020,1115 R330.2@7084.88,1115
NetR331_2: R331.2 U24.15 | length 560.7
  L1-TOP w10: U24.15@6703.43,1180 v1(6810,1180)
  L6-BOT w10: v1(6810,1180) 6900,1180 6980,1100 6980,1064.64 6967.29,1051.93 6967.29,1047.29 6950,1030 6950,1010 6980,980 7035,980 7050,995 R331.2@7079.88,995
NetR332_2: R332.2 U24.1 | length 2092
  L1-TOP w10: v1(6405,1240) 6496.57,1240 U24.1@6506.57,1230
  L3-Signal w10: v1(6405,1240) 6375,1210 6375,1145 6755,765 6755,764.04 6880,639.04 6880,380 6935,325 7035,325 7080,370 7080,710 v1(6955,835) v1@6950,835
  L6-BOT w10: v1(6955,835) 6995,875 R332.2@7079.88,875
NetR333_2: R333.2 U25.8 U25.16 | length 998.1
  L1-TOP w25: v1(6970,2665) 7025.16,2720.16 U25.16@7055,2720.16 ; U25.8@7405,2489.84 7405,2430 v1(7420,2415)
  L3-Signal w25: v1(6970,2665) 7050,2665 7100,2615 7285,2615 7385,2515 7385,2450 v1(7420,2415)
  L6-BOT w25: 6970,2679.88 v1(6970,2665) 7085.12,2780.12 R333.2@7085.12,2820
NetR335_2: R335.2 U25.6 U25.14 | length 836.2
  L1-TOP w25: v1(7175,2810) 7175,2790 7155,2770 7155,2665 7205,2615 7275,2615 7305,2585 U25.6@7305,2489.84
  L6-BOT w25: v1(7175,2810) 7175,2850 7085,2940 7080,2940 7080,3035 7170.12,3125.12 R335.2@7180,3125.12
NetR338_2: R338.2 U38.10 | length 4612.6
  L4-Signal w10: v1(4960,2795) 4960,2680 4993,2647 5088,2647 5218,2517 5668,2517 5695,2490 5695,1760 5753,1702 6132.96,1702 6245.96,1815 6390.96,1815 6455.96,1880 6640,1880 6835,2075 6965,2075 7195,2305 7415,2305 7510,2400 7510,2890 7475,2925 v1(7465,2925)
  L6-BOT w10: v1@4955,2785 4955,2790 4960,2785 U38.10@4960,2694.84 ; R338.2@7394.88,3070 7394.88,2995.12 v1(7465,2925)
NetR339_1: R339.1 U25.12 | length 992.3
  L1-TOP w10: U25.12@7255,2720.16 7255,2745 v1(7305,2795)
  L6-BOT w10: v1(7305,2795) 7350,2840 7390,2840 7405,2825 7405,2725 7540,2590 7540,2305 7465,2230 R339.1@7375.12,2230
NetR342_2: R342.2 U39.16 | length 3432
  L4-Signal w10: v1(5245,2270) 5280,2270 5548,2002 5548,1906.08 5425,1783.08 5425,1620 5505,1540 6175,1540 6291,1656 7181,1656 7213,1688 7293,1688 7360,1755 7600,1755 v1(7640,1715) ; 7630,1700 v1@7645,1715
  L6-BOT w10: U39.16@5235,2384.84 5235,2280 v1(5245,2270) ; R342.2@7555.12,1730 7570.12,1715 v1(7640,1715)
NetR343_2: R343.2 R351.2 U26.5 | length 555.4
  L1-TOP w10: U26.5@7300.16,550 7360,550 v1(7375,565)
  L6-BOT w10: v1(7375,565) 7395,565 7510,680 7570,680 7585.12,695.12 R343.2@7585.12,765 7635.12,815 R351.2@7704.88,815
NetR344_2: R344.2 R353.2 U26.3 | length 661.8
  L1-TOP w10: U26.3@7300.16,450 7355,450 7365,440 v1(7385,440)
  L6-BOT w10: v1(7385,440) 7465,440 7510,395 7510,335 7530,315 7660,315 7685.12,340.12 R344.2@7685.12,385 7744.88,385 R353.2@7794.88,435
NetR346_2: R346.2 U39.10 | length 3784.2
  L4-Signal w10: 5540,2275 v1(5525,2275) 5525,2255 5490,2220 5490,2215 5606,2099 5606,1886 5479,1759 5479,1639.08 5519.08,1599 6160.92,1599 6251.92,1690 7150,1690 7700,2240 v1(7845,2240)
  L6-BOT w10: v1(5525,2275) 5535,2285 U39.10@5535,2384.84 ; R346.2@7620,2314.88 7694.88,2240 v1(7845,2240)
NetR347_2: R347.2 U39.12 | length 4446.6
  L3-Signal w10: v1(5435,2270) 5435,2240 5565,2110 5565,1899.04 5445,1779.04 5445,1625 5505,1565 6140.96,1565 6265.96,1690 6490,1690 6510,1670 6880,1670 7033,1823 7487,1823 7525,1785 7525,1415 7565,1375 7600,1375 7760,1535 7760,1765.96 7580,1945.96 v1(7580,1985)
  L6-BOT w10: U39.12@5425,2355 5425,2280 v1(5435,2270) ; v1(7580,1985) 7580,1995 7610.12,2025.12 R347.2@7710,2025.12
NetR348_2: R348.2 SW3.2 SW3.4 U31.1 | length 2804.5
  L1-TOP w10: SW3.2@7837.17,1668.74 SW3.2@7837.17,1682.84 ; SW3.2@7866.26,1668.74 SW3.4@7482.83,1668.74 7469.09,1655 7340,1655 7290,1705 6985,1705 6940,1660 6940,1465 6970,1435 7344.04,1435 7404.04,1495 7405,1495 7405,1555 7415,1565 7550,1565 7590,1525 v1(7590,1500) 7685,1405 7984.72,1405 U31.1@8032.81,1356.92 7991.92,1356.92 7910,1275 v1(7885,1275)
  L6-BOT w10: R348.2@7775.12,1330 7855,1330 7885,1300 v1(7885,1275)
NetR349_2: R349.2 SW4.2 SW4.4 U31.3 | length 785.8
  L1-TOP w10: SW4.2@7482.83,1211.26 SW4.4@7837.17,1211.26 7875,1173.43 v1(7875,1145) ; SW4.4@7845,1210 7875,1210 7940,1275 8014.72,1275 U31.3@8032.81,1256.92
  L6-BOT w10: R349.2@7775.12,1211.26 7808.74,1211.26 v1(7875,1145)
NetR356_2: R356.2 U31.12 | length 436.4
  L1-TOP w10: v1(8145,1145) 8251.21,1145 U31.12@8263.12,1156.92
  L6-BOT w10: R356.2@7960,1334.88 7960,1285 8020,1225 8100,1225 8145,1180 v1(8145,1145)
NetR357_2: R357.2 U39.14 | length 4106.1
  L4-Signal w10: v1(5335,2270) 5340,2270 5565,2045 5565,1899.04 5445,1779.04 5445,1625 5505,1565 6175,1565 6283,1673 7173,1673 7205,1705 7285,1705 7475,1895 7735,1895 8135,2295 8135,2360 v1(8130,2365)
  L6-BOT w10: v1(5335,2270) U39.14@5335,2384.84 ; R357.2@8050,2435.12 8059.88,2435.12 v1(8130,2365)
NetR360_2: R360.2 U38.16 | length 5460.2
  L4-Signal w10: v1(4660,2790) 4660,2680 4750,2590 5070,2590 5200,2460 5615.96,2460 5643,2432.96 5643,1727 5728,1642 6153.92,1642 6241.92,1730 6790,1730 6900,1840 7075,1840 7125,1890 7125,2070 7175,2120 7275,2120 7400,2245 7580,2245 7930,2595 8285,2595 v1(8325,2555)
  L6-BOT w10: U38.16@4660,2694.84 v1(4660,2790) ; R360.2@8120,2614.88 8140.12,2614.88 8170,2585 8295,2585 v1(8325,2555)
NetR362_2: R362.2 U31.10 | length 377.3
  L1-TOP w10: v1(8195,1085) 8205,1085 8233.08,1056.92 U31.10@8263.12,1056.92
  L6-BOT w10: R362.2@8080,1334.88 8080,1280 8195,1165 v1(8195,1085)
NetR363_2: R363.2 U34.5 | length 168
  L1-TOP w10: U34.5@8755.6,1271.92 8755.6,1344.56 v1(8757.96,1346.92)
  L6-BOT w10: R363.2@8753.08,1256.92 8757.96,1261.8 v1(8757.96,1346.92)
NetR367_2: R367.2 U10.16 | length 7375.6
  L1-TOP w10: v1(4485,2735) 4520,2700 U10.16@4520,2642.84
  L3-Signal w10: v1(4485,2735) 4500,2720 4500,2705 4555,2650 5090,2650 5220,2520 5660,2520 5695,2485 5695,1755 5745,1705 6184.79,1705 6310,1830.21 6310,2215 6175,2350 6175,2510 6215,2550 6800,2550 6840,2590 7050,2590 7255,2385 7255,2360 7276,2339 7405.92,2339 7436.92,2370 7555,2370 7680,2495 7680,2560 7730,2610 v1(9155,2610)
  L6-BOT w10: R367.2@8744.88,2840 8760,2840 8900,2700 9075,2700 9155,2620 v1(9155,2610)
NetR368_2: R368.2 U18.10 | length 4974.5
  L1-TOP w10: v1(5285,2320) U18.10@5285,2384.84
  L3-Signal w10: v1(5285,2320) 5285,2265 5548,2002 5548,1906.08 5425,1783.08 5425,1615 5500,1540 6140,1540 6270,1670 6475,1670 6495,1650 6885.96,1650 7041.96,1806 7424,1806 7440,1790 7440,1425 7510,1355 7765,1355 7985,1575 v1@8585,1575
  L6-BOT w10: v1(8590,1565) 8789.88,1565 R368.2@8814.88,1540
NetR370_2: R370.2 U34.4 | length 206.4
  L1-TOP w10: U34.4@8960.33,1271.92 9030.44,1342.04 v1(9042.85,1342.04)
  L6-BOT w10: R370.2@8947.96,1342.04 v1(9042.85,1342.04)
NetR372_2: R372.2 U18.12 | length 5674
  L1-TOP w10: v1(5385,2320) U18.12@5385,2384.84 ; v1(9030,1565) 9040,1565 9044.88,1560.12
  L3-Signal w10: v1(5385,2320) 5385,2325 5350,2360 5195,2360 5150,2315 5150,1980 5115,1945 5115,1500 5235,1380 6080,1380 6290,1590 6435,1590 6555,1470 6890,1470 6935,1425 7325,1425 7372,1378 7372,1358 7525,1205 7720,1205 7954,1439 8104,1439 8169,1504 8501.96,1504 8545.96,1460 8670,1460 8714,1504 8969,1504 v1(9030,1565)
  L6-BOT w10: v1(9030,1565) 9030,1560 9044.88,1545.12 R372.2@9044.88,1490
NetR376_1: R376.1 U35.13 | length 304.3
  L1-TOP w10: U35.13@9395,3181.1 9395,3045 v1(9435,3005)
  L6-BOT w10: v1(9435,3005) 9445,3005 9485.12,2964.88 R376.1@9485.12,2920
NetR377_2: R377.2 U36.5 | length 175.1
  L1-TOP w10: U36.5@9700.6,1266.92 9702.96,1269.28 v1(9702.96,1346.92)
  L6-BOT w10: R377.2@9693.08,1256.92 9693.08,1337.04 v1(9702.96,1346.92)
NetR381_2: R381.2 U36.4 | length 194.4
  L1-TOP w10: U36.4@9905.33,1266.92 9970.33,1331.92 v1@9977.96,1331.92
  L6-BOT w10: R381.2@9892.96,1337.04 v1(9987.85,1337.04)
NetSW1_8: SW1.8 U17.6 | length 3605.1
  L1-TOP w10: SW1.8@2860,2091.22 2915,2036.22 2915,1700 v1(2895,1680) ; U17.6@5345,1114.84 v1(5345,1185)
  L6-BOT w10: v1(2895,1680) 2920,1655 3165,1655 3215,1705 3510,1705 3610,1605 3675,1605 3803,1733 4004.7,1733 4027.7,1710 4150,1710 4467,1393 4857,1393 5085,1165 5115,1165 5130,1150 5130,1030 5145,1015 5310,1015 5345,1050 v1(5345,1185)
NetSW2_8: SW2.8 U17.4 | length 2685.1
  L1-TOP w10: v1(5055,855) 5055,945 5080,970 5175,970 5200,995 5200,1040 5245,1085 U17.4@5245,1114.84
  L3-Signal w10: SW2.8@3029.29,1055 3070,1055 3110,1015 3385,1015 3470,1100 3470,1145 3500,1175 3560,1175 3580,1155 3580,1115 3610,1085 4650,1085 4775,960 4910,960 5015,855 v1(5055,855)
NetU5_1: U5.1 U22.8 | length 3996.8
  L1-TOP w10: U5.1@2525,563.43 2666.57,563.43 2680,550 2820,550 3058,788 3483,788 3605,910 v1(3605,1000) ; v1(5895,775) 5895,725 5945,675 U22.8@5974.84,675
  L3-Signal w10: v1(3605,1000) 3600,1000 3665,935 3745,935 3800,990 4460,990 4675,775 5130,775 5230,875 5795,875 v1(5895,775)
NetU11_1: U11.1 U22.6 | length 2359.4
  L1-TOP w10: v1(4380,1425) 4414.88,1390.12 U11.1@4441.57,1390.12 ; U22.6@5974.84,775 v1(6040,775)
  L3-Signal w10: v1(4380,1425) 4540,1425 4845,1120 4920,1120 5105,935 5715,935 5840,1060 6015,1060 6080,995 6080,820 6040,780 v1(6040,775)
NetU12_14: U12.14 U21.8 | length 2299.5
  L1-TOP w10: v1(4415,1705) 4418.43,1708.43 U12.14@4620,1708.43 ; U21.8@5925,1114.84 5939.84,1114.84 v1(5990,1165)
  L3-Signal w10: v1(4415,1705) 4415,1680 4645,1450 4645,1420 5113,952 5697,952 5910,1165 v1(5990,1165)
NetU14_13: U14.13 U21.4 | length 2882.5
  L1-TOP w10: U14.13@4868.43,2515 4915,2515 4950,2480 v1(4950,2450) ; U21.4@5725,1114.84 v1(5725,1185)
  L3-Signal w10: v1(4950,2450) 5000,2400 5000,2315 4910,2225 4610,2225 4545,2160 4545,2100 4675,1970 4675,1470 5080,1065 5525,1065 5645,1185 v1(5725,1185)
NetU15_1: U15.1 U21.2 | length 1891.1
  L1-TOP w10: v1(4600,2130) U15.1@4676.57,2130 ; v1(5505,1185) 5600,1185 5625,1160 U21.2@5625,1114.84
  L3-Signal w10: v1(4600,2130) 4730,2000 4730,1745 4785,1690 4785,1455 5110,1130 5450,1130 v1(5505,1185) v1@5505,1195
NetU15_13: U15.13 U21.6 | length 2019.8
  L1-TOP w10: v1(4775,2140) 4775,2135 4830,2080 U15.13@4873.43,2080 ; U21.6@5825,1114.84 v1(5825,1180)
  L3-Signal w10: v1(4775,2140) 4800,2140 4925,2015 4925,1675 5050,1550 5050,1240 5065,1225 5740,1225 5785,1180 v1(5825,1180)
NetU16_1: U16.1 U17.2 | length 754.6
  L1-TOP w10: U16.1@4731.57,1010 4760,1010 4813,1063 4813,1258 4870,1315 4975,1315 5145,1145 U17.2@5145,1114.84
NetU20_14: U20.14 U22.4 | length 1113.8
  L1-TOP w10: U20.14@5458.43,760 5505,760 5536,729 5536,584 5605,515 v1(5605,480) ; U22.4@5974.84,875 v1(6040,875)
  L3-Signal w10: v1(5605,480) 5700,480 5730,510 5730,565 5810,645 5895,645 5995,745 5995,805 6040,850 v1(6040,875)
NetU22_2: U22.2 U37.14 | length 2678.1
  L1-TOP w10: v1(5910,1000) 5935,975 U22.2@5974.84,975
  L3-Signal w10: v1(4455,580) 4265,580 4200,645 4200,755 4230,785 4390,785 4450,725 4850,725 4888,687 5257,687 5295,725 5295,745 5320,770 5410,770 5450,730 5920,730 5965,775 5965,945 v1(5910,1000)
  L6-BOT w10: v1(4455,580) 4455,575 4488.43,541.57 U37.14@4500,541.57
NetU23_6: U23.6 U41.4 | length 278.3
  L1-TOP w25: v1(6190,3040) v1@6190.71,3039.29
  L1-TOP w40: v1@6190.71,3039.29 U23.6@6250,3039.29
  L6-BOT w40: v1(6190,3040) 6380.71,3040 U41.4@6400,3059.29
NetU25_2: U25.2 U41.1 | length 665.2
  L1-TOP w10: v1(6675,2680) 6675,2635 6720,2590 7070,2590 7105,2555 U25.2@7105,2489.84
  L6-BOT w10: U41.1@6600,2720.71 6634.29,2720.71 v1(6675,2680)
NetU28_10: U28.10 U28.13 | length 392.9
  L1-TOP w10: U28.10@8158.43,1590 8230,1590 8315,1675 8315,1705 8280,1740 U28.13@8158.43,1740
"NORTH CURRENT": J3.26 R248.1 TP17.1 | length 4388.8
  L4-Signal w10: TP17.1@3230,3080 3155,3155 2847.12,3155 2705,3297.12 2705,3865 2770,3930 4000,3930 4080,3850 J3.26@4080,3820
  L6-BOT w10: TP17.1@3230,3080 3160,3010 3015,3010 2995,3030 2995,3120 3060,3185 3565,3185 3620,3130 3620,2540 3689.88,2470.12 R248.1@3705,2470.12
"NORTH DRIVE+": C60.2 J3.10 R10.1 TP6.1 | length 3636
  L1-TOP w10: TP6.1@1220,2490 1260,2450 R10.1@1364.88,2450
  L3-Signal w10: TP6.1@1220,2490 1540,2810 2340,2810 2487,2957 2487,3270.83 2581.17,3365 2910,3365 3168,3623 3373,3623 3425,3675 3425,3750 3405,3770 3330,3770 J3.10@3280,3820 J3.10@3265,3820
  L6-BOT w10: TP6.1@1220,2490 1330,2490 1469.53,2629.53 C60.2@1469.53,2653.11
"NORTH DRIVE-": C59.2 J3.11 R9.1 TP5.1 | length 3468.5
  L1-TOP w10: TP5.1@1220,2710 1374.88,2555.12 R9.1@1590,2555.12
  L3-Signal w10: TP5.1@1220,2710 1280,2710 1398,2828 2328,2828 2470,2970 2470,3277.88 2575.12,3383 2902.04,3383 3159.04,3640 3194.04,3640 3224.04,3670 3330,3670 J3.11@3380,3720
  L6-BOT w10: TP5.1@1220,2710 1335,2710 1398.11,2773.11 C59.2@1469.53,2773.11
"NORTH OC LATCH": J4.22 U27.13 | length 813.9
  L1-TOP w10: v1(7775,3110) U27.13@7775,3191.1
  L3-Signal w10: J4.22@7720,3820 7775,3765 v1(7775,3110)
"NORTH TACH OUT": C11.1 C13.1 J4.47 R44.2 R218.1 R219.1 U3.1 | length 14484.9
  L1-TOP w10: v1(1975,2770) 1988.23,2783.23 C11.1@2074.65,2783.23 2074.65,2829.65 2113.11,2868.11 C13.1@2189.53,2868.11 2189.53,2805.47 v1(2250,2745) ; C11.1@2079.53,2788.11 2129.65,2788.11 2186.22,2731.54 U3.1@2186.22,2698.11 ; R44.2@2654.65,1748.23 2654.65,1733.11 2724.65,1663.11 2724.65,1523.11 2719.65,1518.11 2699.65,1518.11
  L4-Signal w10: v1(2865,3560) 3005,3560 3110,3455 3490,3455 3560,3525 v1(3560,3540)
  L3-Signal w10: v1(2250,2745) 2300,2745 2510,2955 2510,3075 2565.96,3130.96 2700,3130.96 3169.04,3600 3515,3600 3560,3555 v1(3560,3540) ; v1(2865,3560) 2825,3520 2625,3520 2605,3540 2605,3910 2725,4030 7215,4030 7295,3950 9030,3950 9070,3910 9070,3775 9020,3725 J4.47@9020,3720
  L6-BOT w10: v1(1975,2770) 1955,2770 1919.65,2805.35 1919.65,2838.11 1951.54,2870 R218.1@2014.88,2870 2014.88,2790.12 2059.88,2745.12 2079.88,2745.12 2150,2675 2150,2600 2100,2550 2055,2550 1995,2610 1890,2610 1885,2605 1885,2410 1805,2330 1805,2225 1825,2205 1910,2205 1935,2180 1935,2125 1785,1975 1785,1905 1760,1880 1760,1635 1775,1620 2220,1620 2240,1600 2240,1435 2255,1420 2255,1245 2280,1220 2660,1220 2710,1270 2710,1487.76 v1(2689.65,1508.11)
"NORTH VEL IN": J3.16 R19.1 | length 5757.1
  L1-TOP w10: R19.1@1949.53,2428.11 1949.53,2370.47 v1(1985,2335)
  L3-Signal w10: v1(1985,2335) 1985,1580 1805,1400 1710,1400 1695,1385 1695,1245 1730,1210 1945,1210 2050,1105 2400,1105 2590,1295 2590,1375 2635,1420 2665,1420 2735,1490 2735,1590 2920,1775 2920,2445 2960,2485 2960,2620 2925,2655 2925,2815 3070,2960 3520.96,2960 3618,3057.04 3618,3338 3708,3428 3708,3587 3630,3665 3630,3745 3580,3795 J3.16@3580,3820
"NORTH VEL OUT": C76.2 J4.16 R36.2 | length 7134.5
  L1-TOP w10: R36.2@2644.65,2878.23 2680,2913.58 v1(2680,3020)
  L4-Signal w10: v1(2785,3560) 2795,3560 2835,3600 2990,3600 3115,3475 3240,3475 v1(3305,3540)
  L3-Signal w10: v1(2680,3020) 2704.04,3020 3159.04,3475 3250,3475 3305,3530 v1(3305,3540) ; v1(2785,3560) 2765,3540 2655,3540 2625,3570 2625,3905 2730,4010 7200,4010 7390,3820 J4.16@7420,3820
  L6-BOT w10: v1(2680,3020) 2684.65,3015.35 C76.2@2684.65,2938.23
NORTH_ENCODER_BUF: J5.5 R139.1 R319.2 | length 3506.2
  L1-TOP w10: v1(6605,645) 6645,605 R139.1@6779.88,605
  L4-Signal w10: v1(6605,645) v1@6615,645
  L3-Signal w10: v1(6605,645) 6605,640 6645,600 6645,470 6585,410 6585,400 6745,240 8920,240 8955,205 9205,205 9280,280 J5.5@9300,280
  L6-BOT w10: v1(6605,645) 6645,605 R319.2@6779.88,605
NORTH_ENCODER_IN: J5.10 R154.1 R351.1 | length 3288.8
  L1-TOP w10: R154.1@7200.12,1230 7250,1230 v1(7285,1265)
  L4-Signal w10: v1(7905,795) 7970,730 8000.96,730 8180.96,550 8290,550 8330,590 8330,590.96 8419.04,680 8580,680 8710,550 9330,550 J5.10@9500,380
  L6-BOT w10: v1(7285,1265) 7315,1265 7370,1210 7370,1145 7430,1085 7760,1085 7890,955 7890,889.04 7949.04,830 8000,830 8020,810 8020,750 8005,735 7965,735 v1(7905,795) 7885,815 R351.1@7815.12,815 R351.1@7815.12,824.88
NORTH_ENCODER_RTN: J5.12 R329.1 R350.1 | length 3266.3
  L4-Signal w10: v1(7975,780) 8188,567 8282,567 8435,720 8615,720 8765,570 8855,570 8920,635 9085,635 9153,567 9207,567 9355,715 9505,715 9600,620 J5.12@9600,380 J5.12@9585,380
  L6-BOT w10: R329.1@7200.12,1230 7235,1230 7260,1205 7320,1205 7350,1175 7350,1125 7430,1045 7750,1045 7815.12,979.88 R350.1@7815.12,935 7820,935 v1(7975,780)
NORTH_OVERCURRENT_LATCH: U27.7 U32.94 | length 1346.9
  L1-TOP w10: U27.7@7725,2828.9 v1(7725,2920) ; v1(8540,2670) 8540,2570 8601.89,2508.11 U32.94@8601.89,2449.21
  L3-Signal w10: v1(7725,2920) 7725,2765 7778,2712 8498,2712 v1(8540,2670)
NORTH_OVERCURRENT_N: TP40.1 U32.33 U40.10 | length 6594.9
  L1-TOP w10: v1(8580,1630) 8580,1735 8621.57,1776.57 U32.33@8621.57,1850.79
  L4-Signal w10: v1(6405,350) 6505,350 6605,450 6968,450 7088,570 7090,570 7155,635 7155,1395 7167,1407 7361.83,1407 7543.83,1225 7895,1225 8207,1537 8487,1537 v1(8580,1630)
  L3-Signal w10: v1(8580,1630) 8580,1645 8610,1675 9169.79,1675 9189.79,1655 9310,1655 9403,1748 9773,1748 9930,1905 9930,2995 9825,3100 TP40.1@9710,3100
  L6-BOT w10: U40.10@6291.57,470 6350,470 6350,385 6385,350 v1(6405,350)
PCGND: J3.50 TP29.1 U9.2 U9.4 U9.6 U9.8 U10.8 | length 785.1
  L1-TOP w10: U9.8@3710,2875.16 3710,2850 3740,2820 4085,2820 4115,2850 v1(4115,2925) 4118.16,2925 U10.8@4170,2873.16 U10.8@4170,2860 ; 3810,2820 U9.6@3810,2875.16 ; 3910,2820 U9.4@3910,2875.16 ; 4010,2820 U9.2@4010,2875.16
RED_TEL_BRAKE_RELEASE_&_AMP_ENABLE: R128.1 R311.2 U32.11 | length 2655.5
  L1-TOP w10: R128.1@6204.88,2590 6204.88,2505.12 v1(6220,2490) ; v1(8200,2235) 8316.92,2235 8362.55,2189.37 U32.11@8420.79,2189.37
  L3-Signal w10: v1(6220,2490) 6525,2490 6922,2093 7468.75,2093 7520.75,2145 7860,2145 7919,2204 8029,2204 8060,2235 v1(8200,2235)
  L6-BOT w10: R311.2@6204.88,2590 6220,2574.88 v1(6220,2490)
RESET: J3.23 R78.1 | length 689.8
  L1-TOP w10: R78.1@4135,3115.12 4135,3180 v1(4160,3205)
  L3-Signal w10: J3.23@3980,3720 3980,3485 4160,3305 v1(4160,3205)
RESET_BUF_N: U19.10 U32.35 | length 4527.4
  L1-TOP w10: v1(5360,1790) 5370,1800 U19.10@5448.43,1800 ; v1(8615,1630) 8615,1740 8660.94,1785.94 U32.35@8660.94,1850.79
  L3-Signal w10: v1(5360,1790) 5360,1755 5408,1707 5408,1602 5490,1520 6145,1520 6275,1650 6470,1650 6490,1630 6890,1630 7049,1789 7396,1789 7423,1762 7423,1412 7500,1335 7770,1335 7925,1490 8080,1490 8145,1555 8535,1555 8565,1525 8615,1525 8635,1545 8635,1585 8615,1605 v1(8615,1630)
SB_CLOCK_WD_ERR_LATCH: U32.68 U35.2 | length 898.2
  L1-TOP w10: U32.68@9019.21,2248.43 9123.43,2248.43 9180,2305 v1(9240,2305) 9280,2345 9280,2635 9220,2695 9140,2695 9095,2740 U35.2@9095,2818.9
SB_CLOCK_WD_ERR_LATCH: J4.41 U35.18 | length 907.1
  L1-TOP w10: v1(9135,3085) 9145,3095 U35.18@9145,3181.1
  L3-Signal w10: J4.41@8720,3720 8720,3560 9135,3145 v1(9135,3085)
SB_CLOCK_WD_ERR_N: U28.2 U32.25 | length 785.9
  L1-TOP w10: U28.2@7961.57,1740 8020,1740 8040,1760 8040,1815 8020,1835 8020,1940 8040,1960 8110.96,1960 8145,1925.96 8145,1875 8170,1850 8305,1850 8368.78,1913.78 U32.25@8420.79,1913.78
  other v1: 8200,1850
SEGND: C110.2 C111.2 C113.2 L4.3 R301.1 R306.2 TP37.1 U10.2 U23.2 U38.2 U38.4 U38.6 U38.8 | length 2298.4
  L1-TOP w10: U10.2@4470,2873.16 4470,2845 4495,2820 4545,2820 4575,2850 4575,2915 ; L4.3@5905,2850 5905,2905 5930,2930 6140,2930 6240,2830 6325,2830 6350,2805 U23.2@6350,2700.71
  L1-TOP w40: v2(5845,2845) 5900,2845 L4.3@5905,2850
  L6-BOT w10: v1(4575,2930) 4635,2870 4990,2870 5010,2890 ; U38.2@4710,2925.16 4710,2890 4730,2870 ; 4810,2870 U38.4@4810,2925.16 ; 4910,2870 U38.6@4910,2925.16 ; R301.1@5730,2835.12 5835.12,2835.12 v2(5845,2845)
  L6-BOT w40: C110.2@5810,2505.98 5908.03,2505.98 6025,2389.02 v2@6025,2285 ; v2(5845,2845) 5885,2885 R306.2@5885,2934.88 ; C111.2@6030,2165.98 v2(6030,2280)
"SOUTH CURRENT": J3.27 R247.1 TP15.1 | length 4023.7
  L4-Signal w10: TP15.1@3080,3080 3030,3130 2848.08,3130 2685,3293.08 2685,3875 2760,3950 4025,3950 4130,3845 4130,3780 4180,3730 J3.27@4180,3720
  L6-BOT w10: TP15.1@3080,3080 3165,3165 3550,3165 3595,3120 3595,2855.96 3470,2730.96 3470,2640 3525,2585 R247.1@3525,2470.12
"SOUTH DRIVE+": C55.2 J3.7 R12.1 TP8.1 | length 3999.1
  L1-TOP w10: TP8.1@1220,2023.11 1246.89,2023.11 1290,1980 R12.1@1394.88,1980
  L3-Signal w10: TP8.1@1220,2023.11 1216.89,2023.11 1135,2105 1135,2816.92 1180.08,2862 2312,2862 2430,2980 2430,3285.96 2561.04,3417 2887,3417 3180,3710 J3.7@3180,3720
  L6-BOT w10: TP8.1@1220,2023.11 1263.11,1980 1350,1980 1455,2085 C55.2@1455,2160
"SOUTH DRIVE-": C58.2 J3.8 R11.1 TP7.1 | length 3751.6
  L1-TOP w10: TP7.1@1220,2270 1274.88,2270 R11.1@1364.88,2180 ; 1449.53,2263.23 1449.65,2263.11
  L3-Signal w10: TP7.1@1220,2263.11 1216.89,2263.11 1155,2325 1155,2810 1190,2845 2320,2845 2450,2975 2450,3281.92 2568.08,3400 2895,3400 3160,3665 3195,3665 3225,3695 3225,3775 J3.8@3180,3820
  L6-BOT w10: TP7.1@1220,2263.11 1230,2273.11 C58.2@1449.53,2273.11
"SOUTH OS LATCH": J4.23 U27.12 | length 783.2
  L1-TOP w10: v1(7825,3065) U27.12@7825,3191.1
  L3-Signal w10: J4.23@7820,3720 7825,3715 v1(7825,3065)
